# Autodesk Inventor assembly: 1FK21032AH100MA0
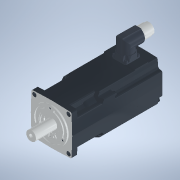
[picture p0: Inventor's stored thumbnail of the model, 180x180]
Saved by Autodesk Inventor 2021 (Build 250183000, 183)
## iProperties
Category: PARTsolutions
Created: 2026-06
Part Number: 1FK21032AH100MA0
Catalog Web Link: www.3dfindit.com
Description: 1FK21032AH100MA0-Servo synchronous motor
Document SubType Name: Assembly
Designer: psAdmin
Mass: 330.521 g
Surface Area: 838.132 cm^2
Volume: 330.521 cm^3
Density: 1 g/cm^3
Title: 1FK21032AH100MA0
Author: Cadenas PARTsolutions
Comments: Servo synchronous motor
PSOL_IDENT_0: {$CADENAS_DATA/23d-libs/siemens_ag/_cat_/12/33/1fk21032ah100ma0.prj},193 {STYP=ASS},{VTYP=3D},{NB=1F
PSOL_IDENT_1: K21032AH100MA0},{LINA=1FK21032AH100MA0},{NN=1FK21032AH100MA0},{DATE=19.08.2025 14:00:27},{GEOMDATE=3
PSOL_IDENT_2: 0.07.2025 02:02:58},{VERSION=},{LINEID=10},{WBVAR=},{WBNUMERIC=}  {NB=1FK21032AH100MA0},{LINA=1FK210
PSOL_IDENT_3: 32AH100MA0},{KT=DUMMY},{PREVIEW=../../../_pool_/d3/78/p_d211_xx_00934j.png},{DESCSHORT=SIMOTICS S-1F
PSOL_IDENT_4: K2 HD, SINAMICS S210 3AC 400V-480V, 0.59 Nm, 4500 rpm},{DESCLONG=SIMOTICS S-1FK2 HD servo motor M0=0
PSOL_IDENT_5: .64 Nm; PN = 0.28 kW at nN=4500 rpm (380-480 V); PN = 0.167 kW at nN=2500 rpm (200-240 V); with hold
PSOL_IDENT_6: ing brake; degree of protection IP64; cylindrical shaft D14 x 30 mm; absolute encoder 22-bit + 12-bi
PSOL_IDENT_7: t multiturn (encoder AM22DQC); with OCC interface; plug size M17, rotatable; SIMOTICS S-1FK2 servomo
PSOL_IDENT_8: torfor a wide range of uses in industrial environments. SIMOTICS S‑1FK2 servomotors are compact sync
PSOL_IDENT_9: hronous motors with a high dynamic performance that set themselves apart as a result of their high p
PSOL_IDENT_10: ower density, degree of protection and overload capability. The motors are available in two variants
PSOL_IDENT_11: : as High Dynamic variant (highest dynamic performance as a result of the low intrinsic moment of in
PSOL_IDENT_12: ertia for applications demanding a high dynamic performance with low moved masses) - and as Compact
PSOL_IDENT_13: variant (precise and stable closed-loop control for medium up to large moved masses as a result of a
PSOL_IDENT_14: medium intrinsic moment of inertia). SIMOTICSS‑1FK2 servomotors fully exploit their strengths in a
PSOL_IDENT_15: system with the SINAMICSS210 frequency converter and simple connection using the one cable connectio
PSOL_IDENT_16: n (OCC). Advantages include the short control and positioning times, fast and precise correction of
PSOL_IDENT_17: disturbing quantities as well as stable control with a high dynamic performance. The servo motors ca
PSOL_IDENT_18: n be configured to address a wide range of requirements. For example with and without holding brake,
PSOL_IDENT_19: IP64 or IP65 degree of protection, singleturn or multiturn absolute encoders - to name just a few.
PSOL_IDENT_20: Further, the servomotors are available in different shaft heights extending from 20 to 100. A shaft
PSOL_IDENT_21: sealing ring is available to achieve an IP65 degree of protection and for subsequent mounting at the
PSOL_IDENT_22: motor or as spare part. SIMOTICS - the optimum motor for each and every motion control application.
PSOL_IDENT_23: },{INTNO=195125315563},{SUPPLIERALTNO=1FK2103-2AH10-0MA0},{MANUID=1FK21032AH100MA0},{MANUNAME=Siemen
PSOL_IDENT_24: s},{MANUTYPEDESC=SYNCHRONOUS MOTOR 1FK2 HD 0,64 NM},{AAU732=SIMOTICS},{AAO057=S-1FK2},{AAU734=SIMOTI
PSOL_IDENT_25: CS S-1FK2 HD servo motor M0=0.64 Nm; PN = 0.28 kW at nN=4500 rpm (380-480 V); PN = 0.167 kW at nN=25
PSOL_IDENT_26: 00 rpm (200-240 V); with holding brake; degree of protection IP64; cylindrical shaft D14 x 30 mm; ab
PSOL_IDENT_27: solute encoder 22-bit + 12-bit multiturn (encoder AM22DQC); with OCC interface; plug size M17, rotat
PSOL_IDENT_28: able;},{AAW338=SYNCHRONOUS MOTOR 1FK2 HD 0,64 NM},{AAO742=SIMOTICS},{AAO663=4034106444723},{NOCUPERO
PSOL_IDENT_29: U=1},{PRICEQUANTITY=1},{QUANTITYMIN=1},{QUANTITYINT=1},{CTN=85015100},{COO=RO},{AAO676=1FK2103-2AH10
PSOL_IDENT_30: -0MA0},{AAO677=Siemens AG},{ORDERUNIT=C62},{CONTENTUNIT=C62}
NB: 1FK21032AH100MA0
NN: 1FK21032AH100MA0
NT: Servo synchronous motor
NBSYN: $MANUID.
LINA: 1FK21032AH100MA0
CATALOG: SIEMENS
PREVIEW: ../../../_pool_/d3/78/p_d211_xx_00934j.png
DESCSHORT: SIMOTICS S-1FK2 HD, SINAMICS S210 3AC 400V-480V, 0.59 Nm, 4500 rpm
DESCLONG: SIMOTICS S-1FK2 HD servo motor M0=0.64 Nm; PN = 0.28 kW at nN=4500 rpm (380-480 V); PN = 0.167 kW at nN=2500 rpm (200-240 V); with holding brake; degree of prot
INTNO: 195125315563
SUPPLIERALTNO: 1FK2103-2AH10-0MA0
MANUID: 1FK21032AH100MA0
MANUNAME: Siemens
MANUTYPEDESC: SYNCHRONOUS MOTOR 1FK2 HD 0,64 NM
AAU732: SIMOTICS
AAO057: S-1FK2
AAU734: SIMOTICS S-1FK2 HD servo motor M0=0.64 Nm; PN = 0.28 kW at nN=4500 rpm (380-480 V); PN = 0.167 kW at nN=2500 rpm (200-240 V); with holding brake; degree of prot
AAW338: SYNCHRONOUS MOTOR 1FK2 HD 0,64 NM
AAO742: SIMOTICS
AAO663: 4034106444723.0
NOCUPEROU: 1
PRICEQUANTITY: 1
QUANTITYMIN: 1
QUANTITYINT: 1
CTN: 85015100
COO: RO
ARTICLENO: 1FK21032AH100MA0
BOMINFO: 1FK21032AH100MA0
CREATOR: CADENAS GmbH
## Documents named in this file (25)
- e:\temp\worker_COMMON_12\temp\tmp_2820_4_ThIIf\format_0\1FK21032AH100MA0.iam
- e:\temp\worker_COMMON_12\temp\tmp_2820_4_ThIIf\format_0\1FK21032AH100MA0_PART1.ipt
- e:\temp\worker_COMMON_12\temp\tmp_2820_4_ThIIf\format_0\1FK21032AH100MA0_PART2.ipt
- e:\temp\worker_COMMON_12\temp\tmp_2820_4_ThIIf\format_0\1FK21032AH100MA0_PART3.ipt
- e:\temp\worker_COMMON_12\temp\tmp_2820_4_ThIIf\format_0\1FK21032AH100MA0_PART4.ipt
- e:\temp\worker_COMMON_12\temp\tmp_2820_4_ThIIf\format_0\1FK21032AH100MA0_PART5.ipt
- e:\temp\worker_COMMON_12\temp\tmp_2820_4_ThIIf\format_0\1FK21032AH100MA0_PART6.ipt
- e:\temp\worker_COMMON_12\temp\tmp_2820_4_ThIIf\format_0\1FK21032AH100MA0_PART7.ipt
- e:\temp\worker_COMMON_12\temp\tmp_2820_4_ThIIf\format_0\1FK21032AH100MA0_PART8.ipt
- e:\temp\worker_COMMON_12\temp\tmp_2820_4_ThIIf\format_0\1FK21032AH100MA0_PART9.ipt
- e:\temp\worker_COMMON_12\temp\tmp_2820_4_ThIIf\format_0\1FK21032AH100MA0_PART10.ipt
- e:\temp\worker_COMMON_12\temp\tmp_2820_4_ThIIf\format_0\1FK21032AH100MA0_PART11.ipt
- e:\temp\worker_COMMON_12\temp\tmp_2820_4_ThIIf\format_0\1FK21032AH100MA0_PART12.ipt
- e:\temp\worker_COMMON_12\temp\tmp_2820_4_ThIIf\format_0\1FK21032AH100MA0_PART13.ipt
- e:\temp\worker_COMMON_12\temp\tmp_2820_4_ThIIf\format_0\1FK21032AH100MA0_PART14.ipt
- e:\temp\worker_COMMON_12\temp\tmp_2820_4_ThIIf\format_0\1FK21032AH100MA0_PART15.ipt
- e:\temp\worker_COMMON_12\temp\tmp_2820_4_ThIIf\format_0\1FK21032AH100MA0_PART16.ipt
- e:\temp\worker_COMMON_12\temp\tmp_2820_4_ThIIf\format_0\1FK21032AH100MA0_PART17.ipt
- e:\temp\worker_COMMON_12\temp\tmp_2820_4_ThIIf\format_0\1FK21032AH100MA0_PART18.ipt
- e:\temp\worker_COMMON_12\temp\tmp_2820_4_ThIIf\format_0\1FK21032AH100MA0_PART19.ipt
- e:\temp\worker_COMMON_12\temp\tmp_2820_4_ThIIf\format_0\1FK21032AH100MA0_PART20.ipt
- e:\temp\worker_COMMON_12\temp\tmp_2820_4_ThIIf\format_0\1FK21032AH100MA0_PART21.ipt
- e:\temp\worker_COMMON_12\temp\tmp_2820_4_ThIIf\format_0\1FK21032AH100MA0_PART22.ipt
- e:\temp\worker_COMMON_12\temp\tmp_2820_4_ThIIf\format_0\1FK21032AH100MA0_PART23.ipt
- e:\temp\worker_COMMON_12\temp\tmp_2820_4_ThIIf\format_0\1FK21032AH100MA0_PART24.ipt
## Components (24 placed, 24 different names)
1. 1FK21032AH100MA0_PART1:1
2. 1FK21032AH100MA0_PART2:1
3. 1FK21032AH100MA0_PART3:1
4. 1FK21032AH100MA0_PART4:1
5. 1FK21032AH100MA0_PART5:1
6. 1FK21032AH100MA0_PART6:1
7. 1FK21032AH100MA0_PART7:1
8. 1FK21032AH100MA0_PART8:1
9. 1FK21032AH100MA0_PART9:1
10. 1FK21032AH100MA0_PART10:1
11. 1FK21032AH100MA0_PART11:1
12. 1FK21032AH100MA0_PART12:1
13. 1FK21032AH100MA0_PART13:1
14. 1FK21032AH100MA0_PART14:1
15. 1FK21032AH100MA0_PART15:1
16. 1FK21032AH100MA0_PART16:1
17. 1FK21032AH100MA0_PART17:1
18. 1FK21032AH100MA0_PART18:1
19. 1FK21032AH100MA0_PART19:1
20. 1FK21032AH100MA0_PART20:1
21. 1FK21032AH100MA0_PART21:1
22. 1FK21032AH100MA0_PART22:1
23. 1FK21032AH100MA0_PART23:1
24. 1FK21032AH100MA0_PART24:1
